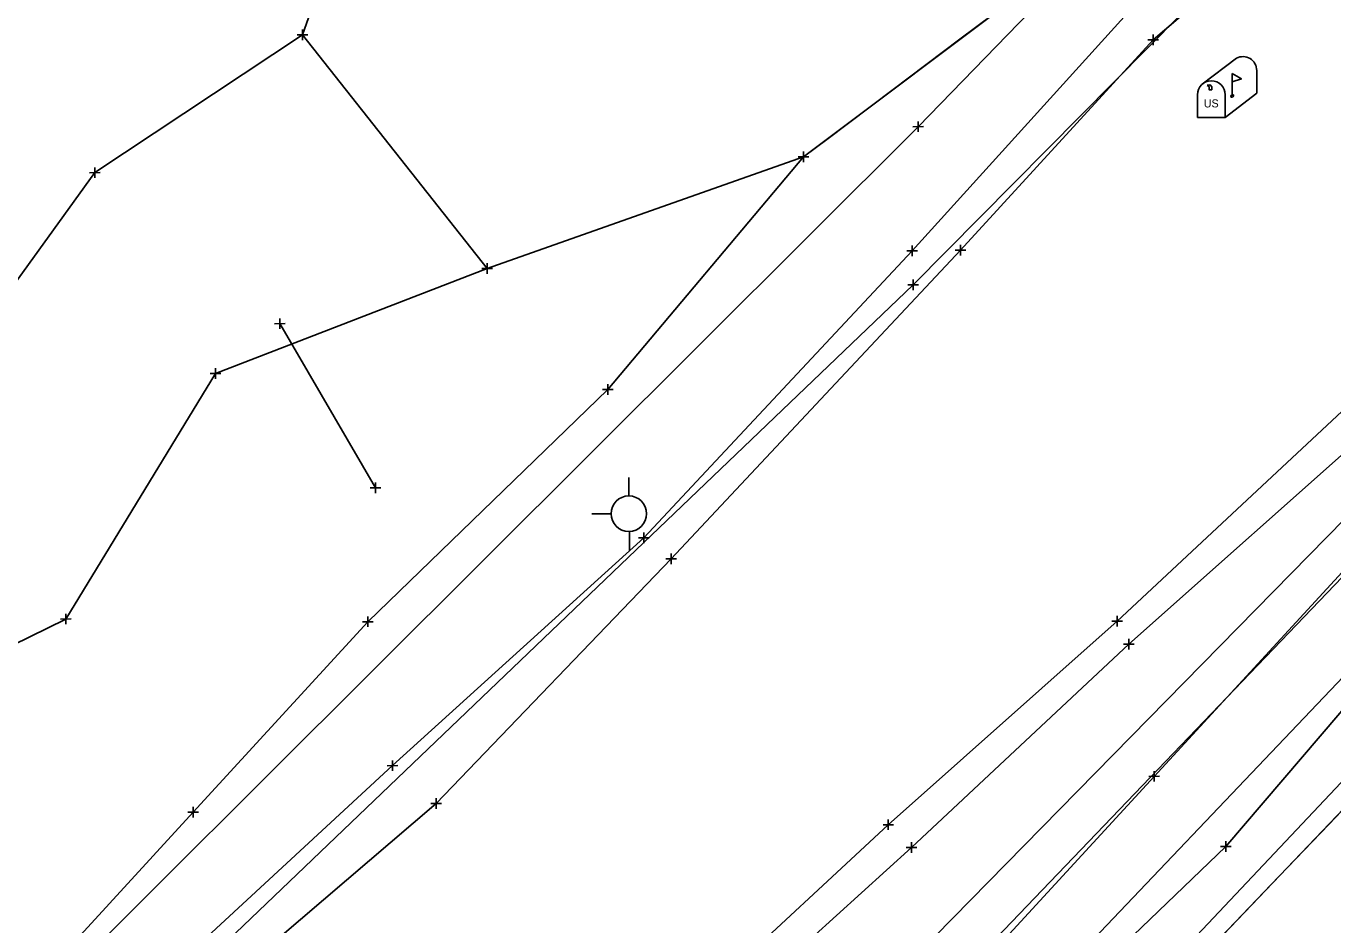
# Model space of a CAD drawing. Extents: x -1 to 1157254, y -1 to 2021979.
# Drawn here: x 1149070.8 to 1149227.6, y 2018634.1 to 2018741.9 of the extents above; entities that cross this region are included whole.
import ezdxf

# ---------------------------------------------------------------- set-up
doc = ezdxf.new("R2010")
doc.units = 0
for name, color, linetype in [('S_BUILDING_ANNOT', 7, 'Continuous'), ('S_CAL_CORNER_ANNOT', 7, 'Continuous'), ('S_CATCH_BASIN', 7, 'Continuous'), ('S_CONTOUR_ANNOT', 7, 'Continuous'), ('S_CROSS_DRAIN', 7, 'Continuous'), ('S_CTL_TABLE', 7, 'Continuous'), ('S_DROP_INLET', 7, 'Continuous'), ('S_DTM_PAVEMENT', 7, 'Continuous'), ('S_EDGE_BITUMINOUS_ANNOT', 7, 'Continuous'), ('S_EDGE_CONCRETE', 7, 'Continuous'), ('S_EXISTING_ALIGNMENT', 7, 'Continuous'), ('S_FENCE', 7, 'Continuous'), ('S_FLAG_POLE', 7, 'Continuous'), ('S_GAS_PUMP_ISLAND_ANNOT', 7, 'Continuous')]:
    doc.layers.add(name, color=color, linetype=linetype)

msp = doc.modelspace()

# ---------------------------------------------------------------- linework, layer by layer
at = {"layer": 'S_BUILDING_ANNOT'}
for p, q in [((1149177.19, 2018729.86), (1149178.47, 2018729.87)), ((1149177.83, 2018729.23), (1149177.83, 2018730.5)), ((1149177.83, 2018729.86), (1149177.83, 2018729.86)), ((1149176.46, 2018714.97), (1149177.73, 2018714.97)), ((1149177.1, 2018714.33), (1149177.1, 2018715.6)), ((1149177.1, 2018714.97), (1149177.1, 2018714.97)), ((1149177.23, 2018710.27), (1149177.23, 2018711.55)), ((1149176.59, 2018710.91), (1149177.87, 2018710.91)), ((1149177.23, 2018710.91), (1149177.23, 2018710.91)), ((1149100.62, 2018706.23), (1149101.89, 2018706.24)), ((1149101.26, 2018705.6), (1149101.25, 2018706.87)), ((1149101.25, 2018706.24), (1149101.25, 2018706.24)), ((1149112.08, 2018686.56), (1149113.36, 2018686.57)), ((1149112.72, 2018685.93), (1149112.72, 2018687.2)), ((1149112.72, 2018686.56), (1149112.72, 2018686.56)), ((1149144.93, 2018679.9), (1149144.92, 2018681.18)), ((1149144.29, 2018680.54), (1149145.56, 2018680.54)), ((1149144.93, 2018680.54), (1149144.93, 2018680.54)), ((1149201.05, 2018670.56), (1149202.32, 2018670.56)), ((1149201.68, 2018669.92), (1149201.68, 2018671.19)), ((1149201.68, 2018670.56), (1149201.68, 2018670.56)), ((1149202.47, 2018667.8), (1149203.74, 2018667.81)), ((1149203.1, 2018667.17), (1149203.1, 2018668.44)), ((1149203.1, 2018667.8), (1149203.1, 2018667.8)), ((1149114.13, 2018653.23), (1149115.4, 2018653.24)), ((1149114.76, 2018652.6), (1149114.76, 2018653.87)), ((1149114.76, 2018653.24), (1149114.76, 2018653.24)), ((1149174.25, 2018645.53), (1149174.25, 2018646.8)), ((1149173.62, 2018646.16), (1149174.89, 2018646.16)), ((1149174.25, 2018646.16), (1149174.25, 2018646.16)), ((1149177.04, 2018642.78), (1149177.04, 2018644.05)), ((1149176.4, 2018643.42), (1149177.67, 2018643.42)), ((1149177.04, 2018643.42), (1149177.04, 2018643.42))]:
    msp.add_line(p, q, dxfattribs=at)
at = {"layer": 'S_CAL_CORNER_ANNOT'}
msp.add_lwpolyline([(1150682.05, 2019865.85), (1150601.54, 2019813.47), (1150510.58, 2019743.97), (1150405.28, 2019665.92), (1150310.69, 2019593.56), (1150188.92, 2019499.64), (1150039.45, 2019388.15), (1149962.15, 2019331.17), (1149944.63, 2019319.08), (1149774.15, 2019191.52), (1149712.73, 2019145.6), (1149665.81, 2019108.74), (1149605.46, 2019057.66), (1149527.46, 2018983.58), (1149450.12, 2018902.93), (1149278.32, 2018738.82), (1149257.2, 2018716.38), (1149237.23, 2018691.25), (1149165.09, 2018617.77), (1149125.26, 2018579.57), (1149069.5, 2018523.84), (1149012.03, 2018473.77), (1148938.88, 2018408.55)], dxfattribs=at)
at = {"layer": 'S_CATCH_BASIN'}
for p, q in [((1149143.11, 2018685.56), (1149143.11, 2018687.81)), ((1149141.02, 2018683.43), (1149138.7, 2018683.43)), ((1149143.19, 2018679.01), (1149143.19, 2018681.34))]:
    msp.add_line(p, q, dxfattribs=at)
msp.add_circle((1149143.12, 2018683.45), 2.13, dxfattribs=at)
at = {"layer": 'S_CONTOUR_ANNOT'}
for points in [[(1149931.59, 2019393.98), (1149688.42, 2019230.92), (1149605.65, 2019167.39), (1149471.25, 2019025.78), (1149394.11, 2018934.21), (1149347.84, 2018899.68), (1149226.01, 2018779.47), (1149177.83, 2018729.86), (1148942.89, 2018495.75), (1148824.88, 2018414.4), (1148656.17, 2018321.62), (1148428.99, 2018204.95), (1148398.58, 2018185.48), (1148319.88, 2018123.12), (1148171.01, 2018007.64), (1148133.82, 2017978.13)], [(1149934.92, 2019374.11), (1149784.56, 2019258.12), (1149678.43, 2019178.13), (1149472.4, 2019004.16), (1149427, 2018951.04), (1149358.36, 2018900), (1149291.74, 2018823.41), (1149233.45, 2018767.69), (1149177.23, 2018710.91), (1149078.39, 2018616.37), (1148964.19, 2018499.8), (1148972, 2018491.15), (1148988.16, 2018467.17), (1149002.28, 2018452.45)]]:
    msp.add_lwpolyline(points, dxfattribs=at)
at = {"layer": 'S_CROSS_DRAIN'}
for p, q in [((1149211.88, 2018734.96), (1149216.01, 2018738.07)), ((1149215.5, 2018736.25), (1149215.5, 2018733.54)), ((1149218.45, 2018736.6), (1149218.45, 2018733.88)), ((1149211.33, 2018733.69), (1149211.33, 2018730.98)), ((1149214.65, 2018730.98), (1149218.45, 2018733.88)), ((1149214.65, 2018733.69), (1149214.65, 2018730.98)), ((1149211.33, 2018730.98), (1149214.65, 2018730.98))]:
    msp.add_line(p, q, dxfattribs=at)
for points in [[(1149215.5, 2018736.25), (1149216.6, 2018735.59), (1149215.5, 2018735.24)], [(1149212.51, 2018734.8), (1149212.73, 2018734.67), (1149212.73, 2018734.28), (1149213.04, 2018734.28), (1149213.04, 2018734.64), (1149212.84, 2018734.89), (1149212.51, 2018734.83)]]:
    msp.add_lwpolyline(points, dxfattribs=at)
for centre, end in [((1149216.78, 2018736.6), 117.5718), ((1149212.99, 2018733.69), 180)]:
    msp.add_arc(centre, 1.66, 0, end, dxfattribs=at)
msp.add_ellipse((1149215.5, 2018733.54), major_axis=(0.145, 0.132), ratio=0.564646, dxfattribs=at)
at = {"layer": 'S_CTL_TABLE'}
for p, q in [((1149103.34, 2018740.89), (1149104.62, 2018740.89)), ((1149103.98, 2018740.25), (1149103.98, 2018741.52)), ((1149103.98, 2018740.89), (1149103.98, 2018740.89)), ((1149206, 2018739.64), (1149206, 2018740.91)), ((1149205.36, 2018740.27), (1149206.64, 2018740.28)), ((1149206, 2018740.27), (1149206, 2018740.27)), ((1149164.07, 2018725.59), (1149164.07, 2018726.87)), ((1149163.44, 2018726.23), (1149164.71, 2018726.23)), ((1149164.07, 2018726.23), (1149164.07, 2018726.23)), ((1149078.43, 2018724.34), (1149079.71, 2018724.35)), ((1149079.07, 2018723.71), (1149079.07, 2018724.98)), ((1149079.07, 2018724.35), (1149079.07, 2018724.35)), ((1149182.92, 2018714.43), (1149182.91, 2018715.7)), ((1149182.28, 2018715.07), (1149183.55, 2018715.07)), ((1149182.91, 2018715.07), (1149182.91, 2018715.07)), ((1149125.5, 2018712.85), (1149126.77, 2018712.85)), ((1149126.14, 2018712.21), (1149126.14, 2018713.48)), ((1149126.14, 2018712.85), (1149126.14, 2018712.85)), ((1149092.91, 2018700.26), (1149094.18, 2018700.26)), ((1149093.55, 2018699.62), (1149093.55, 2018700.89)), ((1149093.55, 2018700.26), (1149093.55, 2018700.26)), ((1149140.61, 2018697.71), (1149140.6, 2018698.98)), ((1149139.97, 2018698.34), (1149141.24, 2018698.34)), ((1149140.61, 2018698.34), (1149140.61, 2018698.34)), ((1149147.56, 2018678.03), (1149148.83, 2018678.03)), ((1149148.2, 2018677.4), (1149148.2, 2018678.67)), ((1149148.2, 2018678.03), (1149148.2, 2018678.03)), ((1149074.96, 2018670.82), (1149076.23, 2018670.83)), ((1149075.6, 2018670.19), (1149075.6, 2018671.46)), ((1149075.6, 2018670.82), (1149075.6, 2018670.82)), ((1149111.18, 2018670.5), (1149112.45, 2018670.5)), ((1149111.81, 2018669.87), (1149111.81, 2018671.14)), ((1149111.81, 2018670.5), (1149111.81, 2018670.5)), ((1149205.5, 2018651.95), (1149206.77, 2018651.96)), ((1149206.14, 2018651.32), (1149206.13, 2018652.59)), ((1149206.13, 2018651.95), (1149206.13, 2018651.95)), ((1149090.85, 2018647.04), (1149090.85, 2018648.31)), ((1149119.39, 2018648.7), (1149120.67, 2018648.71)), ((1149120.03, 2018648.07), (1149120.03, 2018649.34)), ((1149120.03, 2018648.7), (1149120.03, 2018648.7)), ((1149090.21, 2018647.68), (1149091.49, 2018647.68)), ((1149090.85, 2018647.68), (1149090.85, 2018647.68)), ((1149214.09, 2018643.55), (1149215.37, 2018643.55)), ((1149214.73, 2018642.92), (1149214.73, 2018644.19)), ((1149214.73, 2018643.55), (1149214.73, 2018643.55))]:
    msp.add_line(p, q, dxfattribs=at)
at = {"layer": 'S_DROP_INLET'}
msp.add_lwpolyline([(1149478.88, 2018922.64), (1149385.84, 2018831.36), (1149330.57, 2018775.16), (1149250.6, 2018696.8), (1149231.5, 2018678.75), (1149169.67, 2018614.3), (1149128.45, 2018577.04), (1149075.89, 2018529.44), (1149016.28, 2018476.33), (1148941.34, 2018408.7), (1148861.11, 2018354.7), (1148778.49, 2018311.96), (1148755.86, 2018297.95), (1148577.39, 2018201.52), (1148460.64, 2018136.54), (1148334.57, 2018041.74), (1148195.53, 2017935.77), (1148138.82, 2017892.99)], dxfattribs=at)
at = {"layer": 'S_DTM_PAVEMENT'}
msp.add_lwpolyline([(1149112.72, 2018686.56), (1149101.25, 2018706.24)], dxfattribs=at)
at = {"layer": 'S_EDGE_BITUMINOUS_ANNOT'}
for points in [[(1149209.66, 2018763.38), (1149190.82, 2018746.34), (1149164.07, 2018726.23), (1149140.61, 2018698.34), (1149111.81, 2018670.5), (1149090.85, 2018647.68), (1149065.98, 2018620.52), (1149040.41, 2018597.78), (1149016.75, 2018573.05), (1149003.31, 2018567.45)], [(1149220.44, 2018752.64), (1149206, 2018740.27), (1149182.91, 2018715.07), (1149148.2, 2018678.03), (1149120.03, 2018648.7), (1149092.97, 2018625.6), (1149054.44, 2018584.44), (1149031.25, 2018561.24), (1149005.32, 2018534.15)], [(1149103.98, 2018740.89), (1149079.07, 2018724.35), (1149056.94, 2018693.7), (1149030.91, 2018690.87), (1149010.95, 2018703.01)], [(1149126.14, 2018712.85), (1149093.55, 2018700.26), (1149075.6, 2018670.82), (1149049.88, 2018658.2), (1149024.62, 2018651), (1149005.72, 2018643.59)], [(1149198.43, 2018543.32), (1149177.74, 2018568.36), (1149152.2, 2018590.43), (1149177.35, 2018620.64), (1149206.13, 2018651.95), (1149239.27, 2018687.96)], [(1149289.06, 2018635.52), (1149277.51, 2018655.95), (1149264.28, 2018681.57), (1149233.98, 2018653.4), (1149210.16, 2018628.53), (1149185.9, 2018602.44), (1149199.11, 2018584.23), (1149216.65, 2018558.95)], [(1149206, 2018552.01), (1149190.25, 2018573.38), (1149170.85, 2018596.74), (1149187.48, 2018617.37), (1149214.73, 2018643.55), (1149244.21, 2018677.98)]]:
    msp.add_lwpolyline(points, dxfattribs=at)
at = {"layer": 'S_EDGE_CONCRETE'}
msp.add_lwpolyline([(1149074.77, 2018555.4), (1149101.25, 2018579.92), (1149110.54, 2018588.04), (1149133.62, 2018609.47), (1149153.56, 2018626.97), (1149174.25, 2018646.16), (1149201.68, 2018670.56), (1149230.43, 2018697.4), (1149256.84, 2018721.32)], dxfattribs=at)
at = {"layer": 'S_EXISTING_ALIGNMENT'}
for points in [[(1149218.86, 2018757.4), (1149203.28, 2018743.89), (1149177.1, 2018714.97), (1149144.93, 2018680.54), (1149114.76, 2018653.24), (1149088.86, 2018629.3), (1149049.48, 2018588.37), (1149027.64, 2018565.72), (1149000, 2018538.04)], [(1149291.36, 2018636), (1149279.15, 2018656.78), (1149262.48, 2018687.06), (1149233.2, 2018656.13), (1149209.26, 2018630.77), (1149183.39, 2018602.59), (1149197.32, 2018582.32), (1149214.28, 2018558.51)]]:
    msp.add_lwpolyline(points, dxfattribs=at)
at = {"layer": 'S_FENCE'}
msp.add_lwpolyline([(1149562.21, 2019005.4), (1149486.21, 2018927.15), (1149466.96, 2018916.4), (1149448.15, 2018887.45), (1149385.38, 2018826.9), (1149357.5, 2018803.66), (1149334.17, 2018772.97), (1149278.68, 2018714.02), (1149266.21, 2018707.99), (1149250.6, 2018696.75), (1149241.46, 2018677.2), (1149179.13, 2018611.74), (1149130.37, 2018567.15), (1149080.16, 2018520.92), (1149020.19, 2018471.53), (1148946.08, 2018397.31), (1148842.28, 2018340.54), (1148783.26, 2018310.71), (1148755.06, 2018299.13), (1148580.09, 2018196.31), (1148464.77, 2018128.06), (1148357.29, 2018049.22), (1148182.05, 2017918.06), (1148146.03, 2017882.74)], dxfattribs=at)
at = {"layer": 'S_FLAG_POLE'}
msp.add_lwpolyline([(1149076.94, 2018552.92), (1149104.61, 2018577.43), (1149113.51, 2018585.24), (1149118.18, 2018586.33), (1149121.83, 2018586.14), (1149127.68, 2018582.67), (1149137.39, 2018591.98), (1149135.22, 2018596.96), (1149135.08, 2018599.33), (1149134.72, 2018602.2), (1149135.71, 2018605.31), (1149156.05, 2018624.39), (1149177.04, 2018643.42), (1149203.1, 2018667.8), (1149232.89, 2018694.27), (1149235.45, 2018695.13), (1149238.24, 2018695.83), (1149241.59, 2018695.32), (1149262.41, 2018710.92), (1149258.99, 2018718.76)], dxfattribs=at)
at = {"layer": 'S_GAS_PUMP_ISLAND_ANNOT'}
for points in [[(1149190.82, 2018746.34), (1149182.84, 2018740.34), (1149174.85, 2018734.33), (1149166.86, 2018728.33), (1149164.07, 2018726.23), (1149126.14, 2018712.85), (1149103.98, 2018740.89), (1149113.35, 2018767.36)], [(1149160.89, 2018518.11), (1149198.43, 2018543.32), (1149216.65, 2018558.95), (1149216.19, 2018559.6), (1149210.5, 2018567.81), (1149204.81, 2018576.02), (1149203.37, 2018621.22), (1149210.16, 2018628.53), (1149213.26, 2018631.77), (1149220.17, 2018638.98), (1149227.08, 2018646.19), (1149233.98, 2018653.4)]]:
    msp.add_lwpolyline(points, dxfattribs=at)

# ---------------------------------------------------------------- texts
at = {"layer": 'S_CROSS_DRAIN'}
msp.add_text('US', height=0.96, dxfattribs=at).set_placement((1149212.09, 2018732.17))

doc.saveas('drawing.dxf')
